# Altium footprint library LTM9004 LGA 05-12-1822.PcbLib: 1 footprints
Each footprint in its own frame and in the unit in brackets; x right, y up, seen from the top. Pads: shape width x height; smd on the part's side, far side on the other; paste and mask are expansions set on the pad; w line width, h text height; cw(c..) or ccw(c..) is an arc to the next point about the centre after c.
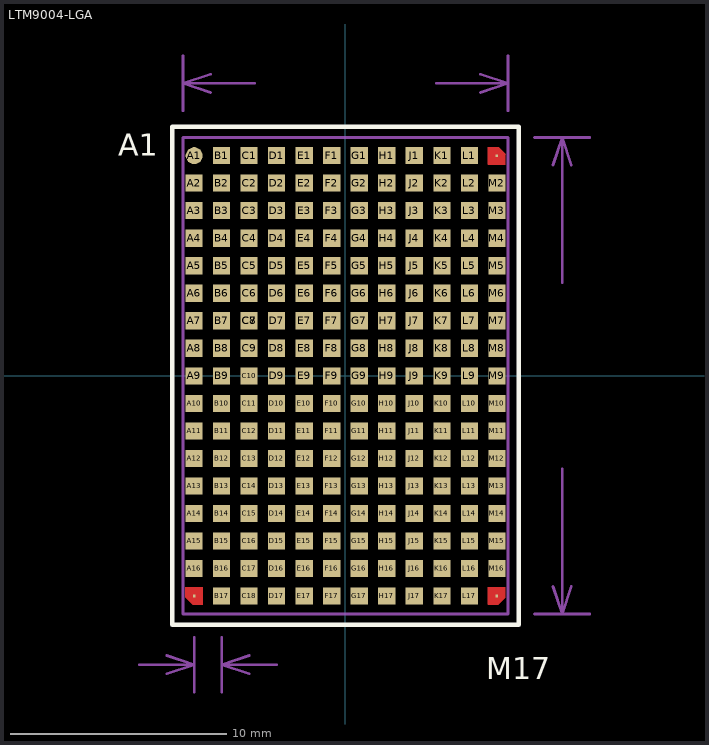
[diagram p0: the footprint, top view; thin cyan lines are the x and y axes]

## LTM9004-LGA [mil]
pads (205):
  round 31 smd paste-3.5 mask-3: A1(-275,400)
  rect 31x31 smd paste-3.5 mask-3: A2(-275,350) A3(-275,300) A4(-275,250) A5(-275,200) A6(-275,150) A7(-275,100) A8(-275,50) A9(-275,0) A10(-275,-50) A11(-275,-100) A12(-275,-150) A13(-275,-200) A14(-275,-250) A15(-275,-300) A16(-275,-350) B1(-225,400) B2(-225,350) B3(-225,300) B4(-225,250) B5(-225,200) B6(-225,150) B7(-225,100) B8(-225,50) B9(-225,0) B10(-225,-50) B11(-225,-100) B12(-225,-150) B13(-225,-200) B14(-225,-250) B15(-225,-300) B16(-225,-350) B17(-225,-400) C1(-175,400) C2(-175,350) C3(-175,300) C4(-175,250) C5(-175,200) C6(-175,150) C7(-175,100) C8(-175,100) C9(-175,50) C10(-175,0) C11(-175,-50) C12(-175,-100) C13(-175,-150) C14(-175,-200) C15(-175,-250) C16(-175,-300) C17(-175,-350) C18(-175,-400) D1(-125,400) D2(-125,350) D3(-125,300) D4(-125,250) D5(-125,200) D6(-125,150) D7(-125,100) D8(-125,50) D9(-125,0) D10(-125,-50) D11(-125,-100) D12(-125,-150) D13(-125,-200) D14(-125,-250) D15(-125,-300) D16(-125,-350) D17(-125,-400) E1(-75,400) E2(-75,350) E3(-75,300) E4(-75,250) E5(-75,200) E6(-75,150) E7(-75,100) E8(-75,50) E9(-75,0) E10(-75,-50) E11(-75,-100) E12(-75,-150) E13(-75,-200) E14(-75,-250) E15(-75,-300) E16(-75,-350) E17(-75,-400) F1(-25,400) F2(-25,350) F3(-25,300) F4(-25,250) F5(-25,200) F6(-25,150) F7(-25,100) F8(-25,50) F9(-25,0) F10(-25,-50) F11(-25,-100) F12(-25,-150) F13(-25,-200) F14(-25,-250) F15(-25,-300) F16(-25,-350) F17(-25,-400) G1(25,400) G2(25,350) G3(25,300) G4(25,250) G5(25,200) G6(25,150) G7(25,100) G8(25,50) G9(25,0) G10(25,-50) G11(25,-100) G12(25,-150) G13(25,-200) G14(25,-250) G15(25,-300) G16(25,-350) G17(25,-400) H1(75,400) H2(75,350) H3(75,300) H4(75,250) H5(75,200) H6(75,150) H7(75,100) H8(75,50) H9(75,0) H10(75,-50) H11(75,-100) H12(75,-150) H13(75,-200) H14(75,-250) H15(75,-300) H16(75,-350) H17(75,-400) J1(125,400) J2(125,350) J3(125,300) J4(125,250) J5(125,200) J6(125,150) J7(125,100) J8(125,50) J9(125,0) J10(125,-50) J11(125,-100) J12(125,-150) J13(125,-200) J14(125,-250) J15(125,-300) J16(125,-350) J17(125,-400) K1(175,400) K2(175,350) K3(175,300) K4(175,250) K5(175,200) K6(175,150) K7(175,100) K8(175,50) K9(175,0) K10(175,-50) K11(175,-100) K12(175,-150) K13(175,-200) K14(175,-250) K15(175,-300) K16(175,-350) K17(175,-400) L1(225,400) L2(225,350) L3(225,300) L4(225,250) L5(225,200) L6(225,150) L7(225,100) L8(225,50) L9(225,0) L10(225,-50) L11(225,-100) L12(225,-150) L13(225,-200) L14(225,-250) L15(225,-300) L16(225,-350) L17(225,-400) M2(275,350) M3(275,300) M4(275,250) M5(275,200) M6(275,150) M7(275,100) M8(275,50) M9(275,0) M10(275,-50) M11(275,-100) M12(275,-150) M13(275,-200) M14(275,-250) M15(275,-300) M16(275,-350)
  rect 5x5 smd paste-3.5 mask-3: A17(-275,-400) M1(275,400) M17(275,-400)
TopLayer:
  region: 259.5,384.5 290.5,384.5 290.5,402.5 277.5,415.5 259.5,415.5
  region: 259.5,-415.5 277.5,-415.5 290.5,-402.5 290.5,-384.5 259.5,-384.5
  region: -290.5,-402.5 -277.5,-415.5 -259.5,-415.5 -259.5,-384.5 -290.5,-384.5
  lines w0.39: -290.5,-402.5 -290.5,-384.5 -259.5,-384.5 -259.5,-415.5 -277.5,-415.5 -290.5,-402.5 ; 259.5,-415.5 259.5,-384.5 290.5,-384.5 290.5,-402.5 277.5,-415.5 259.5,-415.5 ; 259.5,384.5 259.5,415.5 277.5,415.5 290.5,402.5 290.5,384.5 259.5,384.5
TopOverlay:
  lines w8: -314.96,-452.76 -314.96,452.76 314.96,452.76 314.96,-452.76 -314.96,-452.76
  text "M17" at 255.91,-551.18 h40
  text "A1" at -412.8,400 h40
Mechanical16:
  lines w5: -375,-525 -275,-525 ; -325,-541.67 -275,-525 ; -325,-508.33 -275,-525 ; -295.28,481.5 -295.28,581.5 ; -275,-575 -275,-475 ; -245.28,514.83 -295.28,531.5 ; -245.28,548.16 -295.28,531.5 ; -225,-575 -225,-475 ; -175,-541.67 -225,-525 ; -175,-508.33 -225,-525 ; -164.95,531.5 -295.28,531.5 ; -125,-525 -225,-525 ; 164.95,531.5 295.28,531.5 ; 245.28,514.83 295.28,531.5 ; 245.28,548.16 295.28,531.5 ; 295.28,481.5 295.28,581.5 ; 343.7,-433.07 443.7,-433.07 ; 343.7,433.07 443.7,433.07 ; 377.03,-383.07 393.7,-433.07 ; 377.03,383.07 393.7,433.07 ; 393.7,-169.12 393.7,-433.07 ; 393.7,169.12 393.7,433.07 ; 410.37,-383.07 393.7,-433.07 ; 410.37,383.07 393.7,433.07 ; -295.28,-433.07 295.28,-433.07 295.28,433.07 -295.28,433.07 -295.28,-433.07
  text "1.27 (mm)" at -450.77,-644.97 h50
  text "15 (mm)" at -154.95,501.5 h50
  text "22 (mm)" at 423.69,-159.12 h50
